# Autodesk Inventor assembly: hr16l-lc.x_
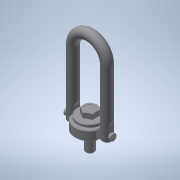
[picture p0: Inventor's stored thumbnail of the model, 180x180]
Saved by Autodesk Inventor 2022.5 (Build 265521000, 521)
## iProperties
Part Number: hr16l-lc.x_
Material: 一般
Document SubType Name: Assembly
Designer: ImaoCorp
Sending System: SOLIDWORKS 2017-2017317
MC: AMD64
MC_MODEL: Intel64 Family 6 Model 60 Stepping 3, GenuineIntel
OS: Windows_NT
FRU: Parasolid Version 29.0, build 201,  4-17-2017
FORMAT: text
GUISE: transmit
KEY: hr16l-lc
FILE: hr16l-lc.x_t
DATE: Mon Jul 01 17:37:35 2019
Author: ImaoCorp
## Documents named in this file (3)
- X:\14_SW2022-Inv2022\00_全2023-1023新製品(TCC)まで\h\hr16l-lc\HR16L-LC.iam
- X:\14_SW2022-Inv2022\00_全2023-1023新製品(TCC)まで\h\hr16l-lc\hr16l-lc_01.ipt
- X:\14_SW2022-Inv2022\00_全2023-1023新製品(TCC)まで\h\hr16l-lc\hr16l-lc_02.ipt
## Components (2 placed, 2 different names)
1. hr16l-lc_01
2. hr16l-lc_02
